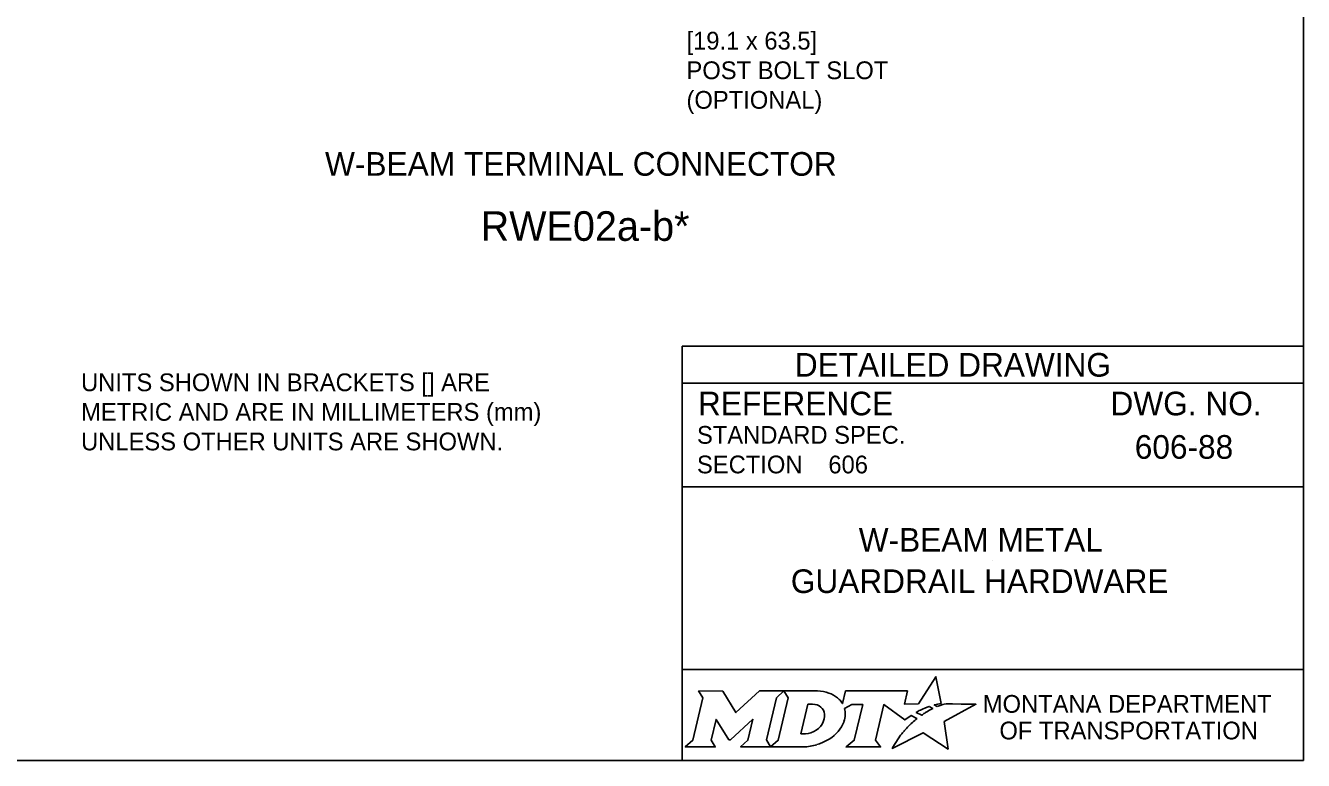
# Model space of a CAD drawing. Extents: x 49991.4 to 50021, y 49987.6 to 50011.4.
# Drawn here: x 50004.296 to 50008.615, y 50000.062 to 50002.547 of the extents above; entities that cross this region are included whole.
import ezdxf

# ---------------------------------------------------------------- set-up
doc = ezdxf.new("R2010")
doc.units = 0
doc.layers.add('Level 1', color=7, linetype='Continuous')
doc.layers.add('Level 2', color=7, linetype='Continuous')

msp = doc.modelspace()

# ---------------------------------------------------------------- linework, layer by layer
at = {"layer": 'Level 1'}
msp.add_lwpolyline([(50008.6146, 50011.2628), (50000.3356, 50011.2628), (50000.3356, 50000.0624), (50008.6146, 50000.0624)], close=True, dxfattribs=at)
at = {"layer": 'Level 2'}
for p, q in [((50008.6146, 50001.4624), (50006.5146, 50001.4624)), ((50006.5146, 50001.4624), (50006.5146, 50000.0624)), ((50006.5146, 50001.4624), (50006.5146, 50000.0624)), ((50008.6146, 50001.3374), (50006.5146, 50001.3374)), ((50008.2507, 50001.1223), (50008.2507, 50001.1223)), ((50007.0089, 50001.0629), (50007.0089, 50001.0629)), ((50008.6146, 50000.9874), (50006.5146, 50000.9874)), ((50007.5646, 50000.7383), (50007.5646, 50000.7383)), ((50008.6146, 50000.3693), (50006.5146, 50000.3693))]:
    msp.add_line(p, q, dxfattribs=at)
for points in [[(50007.3771, 50000.2447), (50007.3668, 50000.2503), (50007.3784, 50000.2531), (50007.39, 50000.2551), (50007.3726, 50000.3452), (50007.3131, 50000.2539), (50007.2658, 50000.2532), (50007.2761, 50000.2973), (50007.0669, 50000.2974), (50007.0568, 50000.2549), (50007.051, 50000.2632)], [(50006.5701, 50000.2974), (50006.5842, 50000.274), (50006.5507, 50000.1307), (50006.525, 50000.1082), (50006.6266, 50000.1082), (50006.6131, 50000.131), (50006.6293, 50000.2011), (50006.673, 50000.1321), (50006.6783, 50000.1321), (50006.7534, 50000.2016), (50006.737, 50000.1305), (50006.7123, 50000.1085), (50006.8139, 50000.1085), (50006.8001, 50000.1318), (50006.8333, 50000.2742)], [(50006.8333, 50000.2742), (50006.8586, 50000.2974), (50006.7762, 50000.2974), (50006.6966, 50000.2244), (50006.6521, 50000.2971), (50006.5701, 50000.2974)], [(50006.9722, 50000.2974), (50006.8586, 50000.2974), (50006.8733, 50000.2745), (50006.8394, 50000.1307), (50006.8139, 50000.1085), (50006.9245, 50000.1085)], [(50006.9962, 50000.2107), (50006.995, 50000.2026), (50006.9918, 50000.1933), (50006.9876, 50000.1851), (50006.982, 50000.1776), (50006.9755, 50000.1707), (50006.9676, 50000.1644), (50006.9593, 50000.1597), (50006.9502, 50000.1558), (50006.9411, 50000.1535), (50006.9319, 50000.1526), (50006.916, 50000.1526), (50006.9396, 50000.2526), (50006.9556, 50000.2526), (50006.9632, 50000.252), (50006.9708, 50000.2501), (50006.9774, 50000.2471), (50006.9835, 50000.2429), (50006.9883, 50000.2379), (50006.992, 50000.2319), (50006.9947, 50000.2257), (50006.9963, 50000.2183), (50006.9963, 50000.2153), (50006.9962, 50000.2107)], [(50007.0636, 50000.2383), (50007.0882, 50000.2514), (50007.1251, 50000.2514), (50007.0965, 50000.1309), (50007.069, 50000.1082), (50007.1852, 50000.1082), (50007.1682, 50000.1311), (50007.1964, 50000.2513), (50007.2677, 50000.1996), (50007.2888, 50000.2147), (50007.3085, 50000.2038)], [(50007.2527, 50000.1479), (50007.2374, 50000.1235), (50007.2327, 50000.116), (50007.2269, 50000.1074), (50007.2246, 50000.1031), (50007.3299, 50000.1562), (50007.4138, 50000.1011), (50007.4007, 50000.1938), (50007.5076, 50000.2522), (50007.4583, 50000.253), (50007.4282, 50000.2534), (50007.4074, 50000.2537), (50007.4006, 50000.2522), (50007.3957, 50000.251), (50007.3873, 50000.2487), (50007.3771, 50000.2447)], [(50007.3267, 50000.2171), (50007.3243, 50000.2154), (50007.306, 50000.225), (50007.3163, 50000.2307), (50007.3204, 50000.2329), (50007.329, 50000.2369), (50007.3347, 50000.2395), (50007.3426, 50000.2425), (50007.3499, 50000.2452), (50007.3617, 50000.2378), (50007.3577, 50000.2357), (50007.3531, 50000.2332), (50007.3489, 50000.231), (50007.3439, 50000.2281), (50007.342, 50000.227), (50007.3393, 50000.2254), (50007.3368, 50000.224), (50007.3345, 50000.2224), (50007.3319, 50000.2206), (50007.3292, 50000.2188), (50007.3267, 50000.2171)], [(50007.2666, 50000.164), (50007.2666, 50000.164)], [(50006.9702, 50000.1158), (50006.9786, 50000.1184), (50006.9916, 50000.1238), (50007.012, 50000.1348)]]:
    msp.add_lwpolyline(points, dxfattribs=at)
for centre, radius, start, end in [((50006.9953, 50000.219), 0.0709, 339.5329, 15.8582), ((50006.9513, 50000.2363), 0.1183, 300.9103, 339.1383)]:
    msp.add_arc(centre, radius, start, end, dxfattribs=at)
for centre, major_axis, ratio, start_param, end_param in [((50006.9701, 50000.25), (0.0834, -0.0037), 0.568097, 0.61298, 1.570796), ((50007.0257, 50000.2573), (0.0361, -0.0295), 0.469099, 1.225588, 1.570796), ((50007.2974, 50000.1941), (-0.0112, -0.0097), 0.021651, 3.157348, 6.283185), ((50007.2597, 50000.1559), (-0.00694, -0.00806), 0.008222, 0, 3.137361), ((50007.2764, 50000.1742), (-0.0098, -0.0102), 0.016458, 3.141593, 6.279097), ((50006.9248, 50000.2568), (0, 0.1484), 0.987302, 3.139398, 3.456847)]:
    msp.add_ellipse(centre, major_axis=major_axis, ratio=ratio, start_param=start_param, end_param=end_param, dxfattribs=at)

# ---------------------------------------------------------------- texts
for s, height, p in [('[19.1 x 63.5]', 0.06, (50006.5294, 50002.4656)), ('POST BOLT SLOT', 0.06, (50006.5294, 50002.3656)), ('(OPTIONAL)', 0.06, (50006.5294, 50002.2656)), ('W-BEAM TERMINAL CONNECTOR', 0.08, (50005.3077, 50002.039)), ('RWE02a-b*', 0.1, (50005.8336, 50001.819)), ('DETAILED DRAWING', 0.0799, (50006.8956, 50001.3599)), ('UNITS SHOWN IN BRACKETS [] ARE ', 0.06, (50004.4832, 50001.3107)), ('REFERENCE', 0.08, (50006.5682, 50001.229)), ('DWG. NO.', 0.08, (50007.9624, 50001.229)), ('METRIC AND ARE IN MILLIMETERS (mm) ', 0.06, (50004.4832, 50001.2107)), ('STANDARD SPEC.', 0.06, (50006.5649, 50001.133)), ('UNLESS OTHER UNITS ARE SHOWN.', 0.06, (50004.4832, 50001.1107)), ('606-88', 0.0799, (50008.0445, 50001.0823)), ('SECTION', 0.06, (50006.5649, 50001.033)), ('606', 0.06, (50007.0089, 50001.0329)), ('W-BEAM METAL', 0.0799, (50007.1116, 50000.7683)), ('GUARDRAIL HARDWARE', 0.0799, (50006.8821, 50000.6284)), ('MONTANA DEPARTMENT', 0.06, (50007.5308, 50000.2236)), ('OF TRANSPORTATION', 0.06, (50007.587, 50000.1336))]:
    msp.add_text(s, height=height, dxfattribs=at).set_placement(p)

doc.saveas('drawing.dxf')
